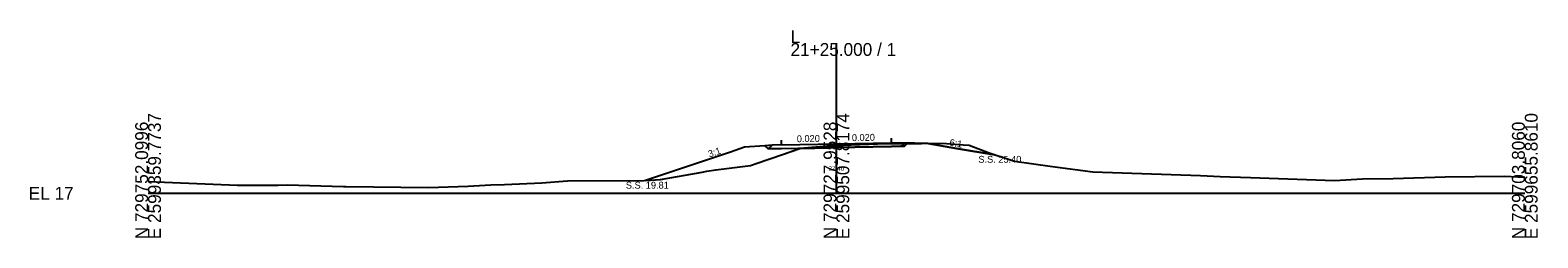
# Model space of a CAD drawing. Extents: x -26 to 3303, y -10 to 9555.
# Drawn here: x 1974.3 to 2302.8, y 2490.3 to 2535.5 of the extents above; entities that cross this region are included whole.
import ezdxf

# ---------------------------------------------------------------- set-up
doc = ezdxf.new("R2010")
doc.units = 0
for name, color, linetype in [('Exist Cross Section Cell', 7, 'Continuous'), ('Exist XS Center Line Elevation Label', 7, 'Continuous'), ('Exist XS Ground Line', 7, 'Continuous'), ('Prop XS Ditch Slope Text', 7, 'Continuous'), ('Prop XS Dump Level', 7, 'Continuous'), ('Prop XS Earthwork Shape', 7, 'Continuous'), ('Prop XS EOT Tick Mark', 7, 'Continuous'), ('Prop XS Finish Grade', 7, 'Continuous'), ('Prop XS Finish Grade Earthwork', 7, 'Continuous'), ('Prop XS Finish Grade Paved Shoulder', 7, 'Continuous'), ('Prop XS Finish Grade Pavement', 7, 'Continuous'), ('Prop XS Pvmt Edge Slope', 7, 'Continuous'), ('Prop XS SE Text', 7, 'Continuous'), ('Prop XS Side Slope Text', 7, 'Continuous'), ('Prop XS SS Elevation Text', 7, 'Continuous'), ('Prop XS Subgrade Earthwork', 7, 'Continuous')]:
    doc.layers.add(name, color=color, linetype=linetype)

msp = doc.modelspace()

# ---------------------------------------------------------------- linework, layer by layer
at = {"layer": 'Exist Cross Section Cell'}
for p, q in [((2150, 2500), (2150, 2532.72)), ((2000, 2500), (2150, 2500)), ((2150, 2500), (2300, 2500))]:
    msp.add_line(p, q, dxfattribs=at)
at = {"layer": 'Exist XS Ground Line'}
msp.add_lwpolyline([(2000, 2502.6), (2019.51, 2501.78), (2028.32, 2501.79), (2030.32, 2501.88), (2042.61, 2501.48), (2043.08, 2501.46), (2061.1, 2501.25), (2069.72, 2501.57), (2074.71, 2501.81), (2077.7, 2501.92), (2085.84, 2502.26), (2091.37, 2502.72), (2108.09, 2502.79), (2111.63, 2502.99), (2120.73, 2504.62), (2121.78, 2504.8), (2123.69, 2505.08), (2131.3, 2506.09), (2132.51, 2506.52), (2138.22, 2508.48), (2142, 2509.79), (2145.52, 2510.08), (2148.67, 2510.35), (2150, 2510.4), (2151.25, 2510.45), (2160.94, 2510.83), (2165.36, 2510.86), (2173.12, 2510.91), (2177.59, 2510.58), (2178.89, 2510.48), (2183.31, 2508.8), (2188.78, 2506.99), (2197.08, 2505.82), (2205.89, 2504.68), (2229.35, 2503.89), (2233.58, 2503.63), (2240.19, 2503.42), (2258.53, 2502.77), (2264.66, 2503.16), (2271.31, 2503.25), (2282.65, 2503.62), (2295.47, 2503.71), (2300, 2503.49)], dxfattribs=at)
at = {"layer": 'Prop XS Dump Level'}
for p, q in [((2138, 2510.54), (2150, 2510.78)), ((2150, 2510.78), (2162, 2511.02))]:
    msp.add_line(p, q, dxfattribs=at)
at = {"layer": 'Prop XS Earthwork Shape'}
for points in [[(2131.3, 2506.09), (2132.51, 2506.52), (2138.22, 2508.48), (2141.98, 2509.79), (2138, 2509.71), (2136, 2509.67), (2135.15, 2509.65), (2134.43, 2510.37), (2130, 2510.02), (2126.91, 2508.99), (2108.37, 2502.81), (2111.63, 2502.99), (2120.73, 2504.62), (2121.78, 2504.8), (2123.69, 2505.08)], [(2134.43, 2510.37), (2130, 2510.02), (2126.91, 2508.99), (2108.37, 2502.81), (2111.63, 2502.99), (2120.73, 2504.62), (2121.78, 2504.8), (2123.69, 2505.08), (2131.3, 2506.09), (2132.51, 2506.52), (2138.22, 2508.48), (2141.98, 2509.79), (2138, 2509.71), (2136, 2509.67), (2135.15, 2509.65)], [(2148.67, 2509.92), (2141.98, 2509.79), (2142, 2509.79), (2145.52, 2510.08), (2148.67, 2510.35)], [(2148.67, 2509.92), (2148.67, 2510.35), (2145.52, 2510.08), (2142, 2509.79), (2141.98, 2509.79)], [(2160.94, 2510.83), (2165.36, 2510.86), (2165.43, 2510.86), (2164.82, 2510.24), (2164, 2510.23), (2162, 2510.19), (2150, 2509.95), (2148.67, 2509.92), (2148.67, 2510.35), (2150, 2510.4), (2151.25, 2510.45)], [(2150, 2509.95), (2162, 2510.19), (2164, 2510.23), (2164.82, 2510.24), (2165.43, 2510.86), (2165.36, 2510.86), (2160.94, 2510.83), (2151.25, 2510.45), (2150, 2510.4), (2148.67, 2510.35), (2148.67, 2509.92)], [(2165.43, 2510.86), (2168.52, 2510.88), (2165.57, 2511)], [(2165.43, 2510.86), (2165.57, 2511), (2168.52, 2510.88)], [(2177.59, 2510.58), (2178.89, 2510.48), (2183.31, 2508.8), (2184.55, 2508.39), (2176.19, 2509.79), (2170, 2510.82), (2168.52, 2510.88), (2173.12, 2510.91)], [(2168.52, 2510.88), (2173.12, 2510.91), (2177.59, 2510.58), (2178.89, 2510.48), (2183.31, 2508.8), (2184.55, 2508.39), (2176.19, 2509.79), (2170, 2510.82)]]:
    msp.add_lwpolyline(points, close=True, dxfattribs=at)
at = {"layer": 'Prop XS EOT Tick Mark'}
for p, q in [((2138, 2510.54), (2138, 2511.54)), ((2162, 2511.02), (2162, 2512.02))]:
    msp.add_line(p, q, dxfattribs=at)
at = {"layer": 'Prop XS Finish Grade'}
for p, q in [((2136, 2510.5), (2134.43, 2510.37)), ((2164, 2511.06), (2165.57, 2511))]:
    msp.add_line(p, q, dxfattribs=at)
at = {"layer": 'Prop XS Finish Grade Earthwork'}
for p, q in [((2130, 2510.02), (2126.91, 2508.99)), ((2134.43, 2510.37), (2130, 2510.02)), ((2165.57, 2511), (2170, 2510.82)), ((2170, 2510.82), (2176.19, 2509.79)), ((2126.91, 2508.99), (2108.37, 2502.81)), ((2176.19, 2509.79), (2184.55, 2508.39))]:
    msp.add_line(p, q, dxfattribs=at)
at = {"layer": 'Prop XS Finish Grade Paved Shoulder'}
for p, q in [((2138, 2510.54), (2136, 2510.5)), ((2162, 2511.02), (2164, 2511.06))]:
    msp.add_line(p, q, dxfattribs=at)
at = {"layer": 'Prop XS Finish Grade Pavement'}
for p, q in [((2138, 2510.54), (2150, 2510.78)), ((2150, 2510.78), (2162, 2511.02))]:
    msp.add_line(p, q, dxfattribs=at)
at = {"layer": 'Prop XS Pvmt Edge Slope'}
for p, q in [((2135.15, 2509.65), (2134.43, 2510.37)), ((2136, 2510.5), (2135.15, 2509.65)), ((2164, 2511.06), (2164.82, 2510.24)), ((2164.82, 2510.24), (2165.57, 2511))]:
    msp.add_line(p, q, dxfattribs=at)
at = {"layer": 'Prop XS Subgrade Earthwork'}
for p, q in [((2135.15, 2509.65), (2134.43, 2510.37)), ((2148.67, 2509.92), (2148.67, 2510.35)), ((2148.67, 2509.92), (2148.67, 2510.35)), ((2150, 2509.95), (2162, 2510.19)), ((2162, 2510.19), (2164, 2510.23)), ((2164, 2510.23), (2164.82, 2510.24)), ((2164.82, 2510.24), (2165.57, 2511)), ((2136, 2509.67), (2135.15, 2509.65)), ((2138, 2509.71), (2136, 2509.67)), ((2148.67, 2509.92), (2138, 2509.71)), ((2148.67, 2509.92), (2150, 2509.95))]:
    msp.add_line(p, q, dxfattribs=at)

# ---------------------------------------------------------------- texts
at = {"layer": 'Exist Cross Section Cell'}
for s, p in [('L', (2140, 2532.72)), ('21+25.000 / 1', (2140, 2529.92)), ('EL 17', (1974, 2498.6))]:
    msp.add_text(s, height=2.8, dxfattribs=at).set_placement(p)
for s, p in [('E 2599359.7737', (2002.8, 2490)), ('E 2599507.8174', (2152.8, 2490)), ('E 2599655.8610', (2302.8, 2490)), ('N 729752.0996', (2000, 2490)), ('N 729727.9528', (2150, 2490)), ('N 729703.8060', (2300, 2490))]:
    msp.add_text(s, height=2.8, rotation=90, dxfattribs=at).set_placement(p)
at = {"layer": 'Exist XS Center Line Elevation Label'}
msp.add_text('27.40', height=1, dxfattribs=at).set_placement((2148.25, 2504.9))
at = {"layer": 'Prop XS Ditch Slope Text'}
msp.add_text('6:1', height=1.5, rotation=350.5377, dxfattribs=at).set_placement((2174.54, 2510.39))
at = {"layer": 'Prop XS Dump Level'}
for s, height, p in [('Case1', 0.04, (2130, 2509.98)), ('Eop', 0.3, (2148.67, 2510.05)), ('Eop', 0.3, (2148.67, 2510.05)), ('Case1', 0.04, (2170, 2510.78))]:
    msp.add_text(s, height=height, dxfattribs=at).set_placement(p)
at = {"layer": 'Prop XS SE Text'}
for p in [(2141.38, 2511.11), (2153.38, 2511.35)]:
    msp.add_text('0.020', height=1.5, rotation=1.1458, dxfattribs=at).set_placement(p)
at = {"layer": 'Prop XS Side Slope Text'}
msp.add_text('3:1', height=1.5, rotation=18.4349, dxfattribs=at).set_placement((2122.33, 2507.78))
at = {"layer": 'Prop XS SS Elevation Text'}
for s, p in [('S.S. 25.40', (2180.93, 2506.65)), ('S.S. 19.81', (2104.11, 2501.01))]:
    msp.add_text(s, height=1.5, dxfattribs=at).set_placement(p)

doc.saveas('drawing.dxf')
